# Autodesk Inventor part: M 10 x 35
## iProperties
IsCustomPart: 0
Created: 2009-02
Part Number: M 10 x 35
Material: 강, 연강
Description: 6각머리 태핑 나사
Document SubType Name: Modeling
Standard: KS B 1003
Designer: KYOUNG IL JANG
Standards Organization: KS
Language: ko-KR
Size Designation: M 10 x 35
Categories: <MemberInstance><Categories><Category DisplayName="조임쇠" InternalName="e4da775c-781d-43d5-af7c-5136215cf5a6" Mnemonic="FSTN"><Category DisplayName="볼트" InternalN
Density: 1 g/cm^3
Author: KYOUNG IL JANG
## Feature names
1. Fillet2
